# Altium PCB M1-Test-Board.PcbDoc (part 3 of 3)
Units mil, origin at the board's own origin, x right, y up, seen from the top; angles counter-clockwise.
Board outline 3977 x 5000 mil, 4 copper layers (Top, GND Layer 2, Power Layer 3, Bottom), stack 60 mil thick; 191 components, 124 nets, 579 pads, 189 vias.
Unrouted connection lines stored in the file: 80.
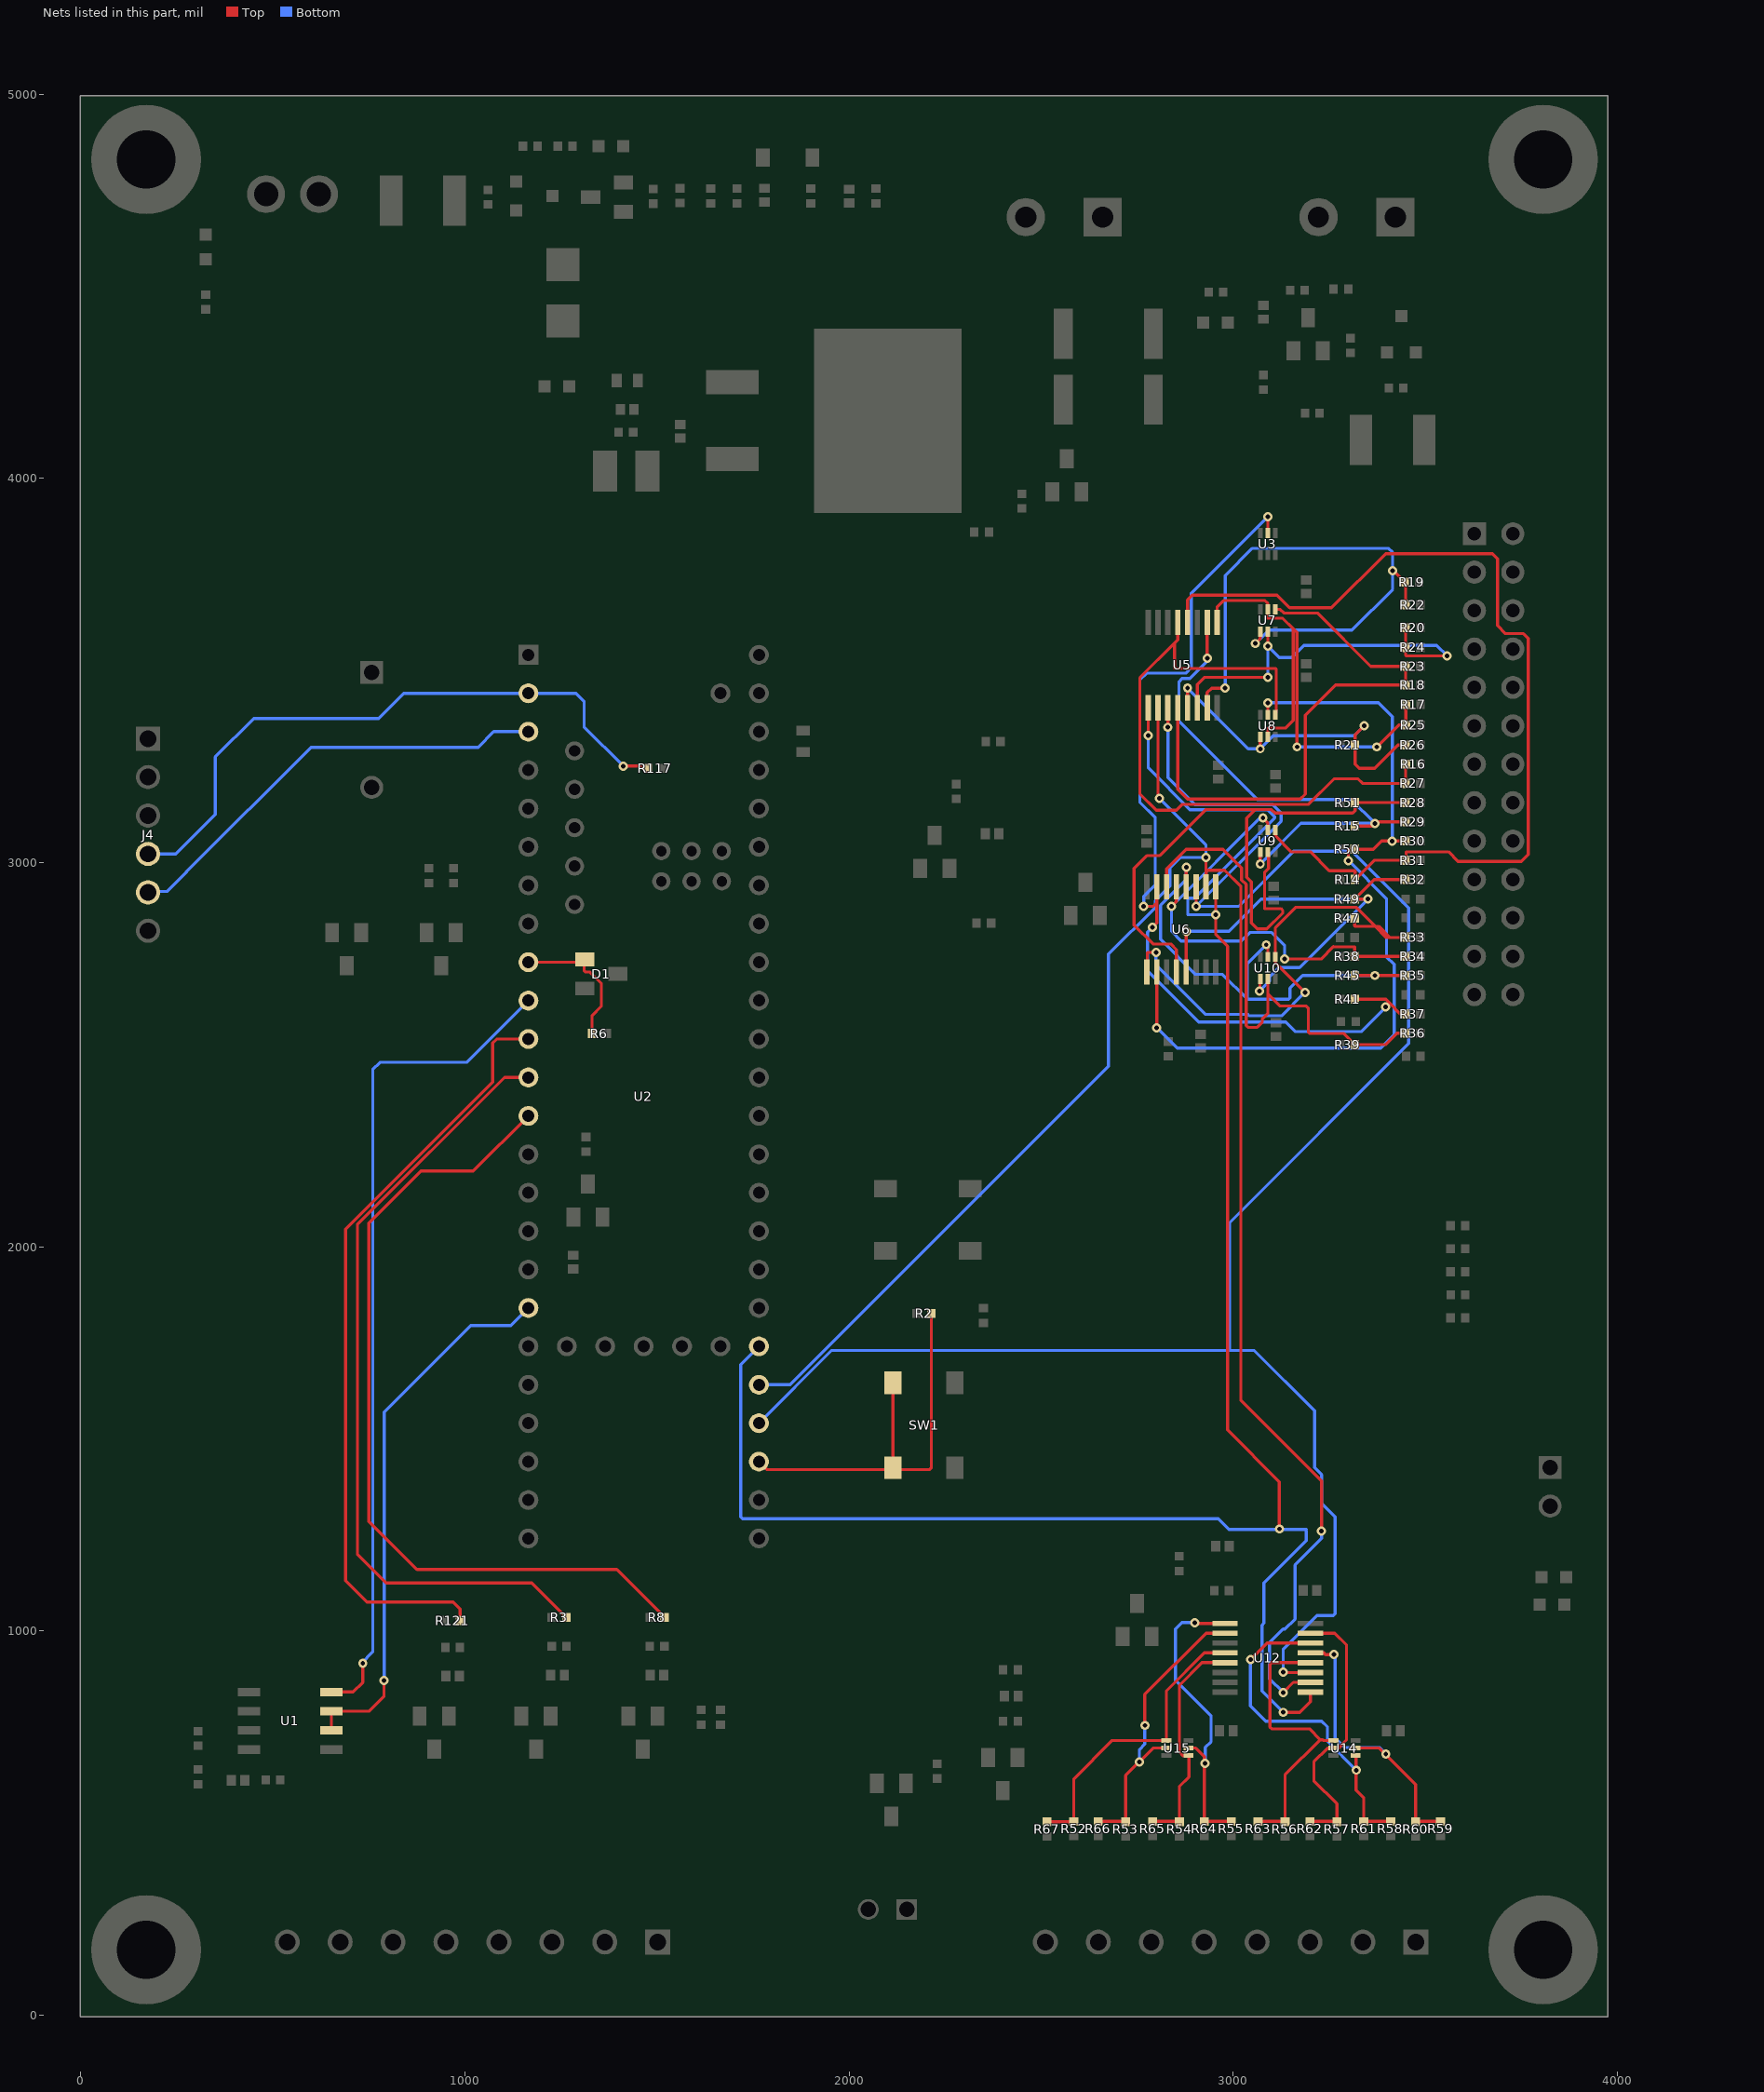
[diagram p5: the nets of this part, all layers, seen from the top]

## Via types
v1: diameter 24, hole 12, Top to Bottom, 186 vias
v2: diameter 50, hole 28, Top to Bottom, 3 vias

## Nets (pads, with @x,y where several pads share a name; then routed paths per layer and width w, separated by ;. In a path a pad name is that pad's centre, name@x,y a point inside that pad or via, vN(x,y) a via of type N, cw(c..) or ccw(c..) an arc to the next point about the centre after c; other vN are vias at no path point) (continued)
NetU2_36: U2.36 U5.11 U6.11 U12.11 | length 5366.6
  Top w8: v1(2830,3352) U5.11@2830,3403 ; v1(2903.39,2886) U6.11@2903.39,2937 ; v1(3130.38,892.95) 3131.72,891.61 U12.11@3201,891.61
  Bottom w8: U2.36@1765.2,1540.63 1954.57,1730 2985.31,1730 ; v1(2830,3352) 2830,3220.93 2900,3150.93 3102.76,3150.93 3125,3128.69 3125,3107.61 v1(2903.39,2886) 3014,2886 3157.64,3029.64 3309.36,3029.64 3457,2882 3457,2529 2990,2062 2990,1734.69 2985.31,1730 ; v1(3130.38,892.95) 3130.38,952.66 3217.72,1040 3260.31,1040 3265,1044.69 3265,1297.16 3230,1332.16 3230,1406.7 3211.7,1425 3211.7,1573.3 3055,1730 2985.31,1730
NetU2_37: U2.37 U5.10 U6.10 U12.10 | length 4949.5
  Top w8: U5.10@2804.41,3403 2804.41,3170.59 v1(2808,3167) ; v1(2928.98,3013) U6.10@2928.98,2937 2929.98,2980 2977.5,2980 3020,2937.5 3020,1600 3230,1390 v1(3230,1260) ; v1(3130.38,839.64) 3156.76,866.02 U12.10@3201,866.02
  Bottom w8: U2.37@1765.2,1640.63 1846.11,1640.63 2675,2469.52 2675,2761.5 2797,2883.5 2797,2900.74 2835,2938.74 2835,2986.07 2861.93,3013 v1(2928.98,3013) 2928.98,3046.02 v1(2808,3167) ; v1(3130.38,839.64) 3094.68,875.33 3094.68,969.68 3130,1005 3135,1005 3160.79,1030.79 3160.79,1171.49 3230,1240.7 v1(3230,1260)
NetU2_38: U2.38 U5.9 U6.9 U12.9 | length 5308.4
  Top w8: v1(2778.82,3331) U5.9@2778.82,3403 ; U6.9@2954.57,2937 v1(2954.57,2864) 2954.57,2812.5 2985.07,2782 2985.07,1522.93 3120,1388 v1@3120,1265 ; v1(3130.38,787.95) 3172.95,787.95 3201,816 U12.9@3201,840.43
  Bottom w8: U2.38@1765.2,1740.63 1717.86,1693.3 1717.86,1296.34 1722.55,1291.66 2961.34,1291.66 2989.08,1263.92 3120.87,1263.92 3190,1263.92 ; v1(2778.82,3331) 2778.82,3246.11 2887.5,3137.43 3089.57,3137.43 3108,3119 3108,3116 2899.5,2907.5 2883,2907.5 2881.89,2906.39 2881.89,2865 2882.89,2864 v1(2954.57,2864) ; v1(3130.38,787.95) 3075,843.33 3075,1015 3080,1020 3080,1080 3080,1125 3190,1235 3190,1260
  other v1: 3120.87,1265.28
P6V-1: R20.2 R24.2 U5.14 U7.5 | length 1054.8
  Top w8: U5.14@2906.77,3403 2906.77,3463.77 2925,3482 v1(3090,3482) ; v1(3090,3563.5) U7.5@3090,3601.06 ; R20.2@3448.91,3611 R24.2@3448.91,3559.79 3448.91,3539 3449.91,3538 v1(3557,3538)
  Bottom w8: v1(3090,3482) v1(3090,3563.5) 3120,3533.5 3152.5,3533.5 3184,3565 3530,3565 v1(3557,3538)
P6V-2: R19.2 R22.1 U5.15 U7.4 | length 1501.3
  Top w8: U5.15@2932.36,3403 2932.36,3442.36 2944,3454 v1(2979,3454) ; v1(3057.81,3570.07) 3070.31,3582.57 U7.4@3070.31,3601.06 ; v1(3415,3760) 3416.69,3760 3445.91,3730.79 R19.2@3445.91,3730 ; R22.1@3448.91,3671 R19.2@3448.91,3727
  Bottom w8: v1(2979,3454) 2979,3747 3050,3818 3404,3818 3415,3807 3415,3711 3309.07,3605.07 3092.81,3605.07 v1(3057.81,3570.07)
P6V-3: R18.2 R23.1 U5.12 U7.1 | length 1509.3
  Top w8: U5.12@2855.59,3403 2855.59,3190.41 2881,3165 3175,3165 3188,3178 3188,3383.5 3266.52,3462.02 R18.2@3448.91,3462.02 R23.1@3448.91,3511 3358,3511 3219.5,3649.5 3131.44,3649.5 3122,3658.94 U7.1@3109.69,3658.94
P12V-1: R17.2 R25.1 U5.1 U7.2 U8.5 | length 1305.6
  Top w8: U5.1@2957.95,3625 2957.95,3664.95 2975,3682 3082.93,3682 3090,3674.93 U7.2@3090,3658.94 3090,3637 3091,3636 3129,3636 3156.18,3608.82 ; U8.5@3090,3327.06 3090,3349 3091,3350 3136,3350 3156.18,3370.18 3156.18,3608.82 ; v1(3166,3301) 3166,3599 3156.18,3608.82 ; v1(3374,3301) 3430.95,3357.95 R25.1@3449.81,3357.95 R17.2@3449.81,3411
  Bottom w8: v1(3166,3301) v1(3374,3301)
P12V-2: R21.2 R26.2 U5.13 U8.4 | length 903.3
  Top w8: U5.13@2881.18,3403 v1(2881.18,3454) ; v1(3070.31,3296.07) U8.4@3070.31,3327.06 ; v1(3341,3356) 3317.09,3332.09 R21.2@3317.09,3306 3317.09,3256.5 3328.59,3245 3368,3245 3429,3306 R26.2@3448.91,3306
  Bottom w8: v1(2881.18,3454) 3039.11,3296.07 v1(3070.31,3296.07) 3104.43,3330.19 3315.19,3330.19 v1(3341,3356)
R_G1: R34.1 R38.1 U6.13 U9.2 | length 1205.9
  Top w8: v1(2839.5,2886) 2852.2,2898.7 U6.13@2852.2,2937 ; v1(3077.5,3115.93) 3090,3103.43 U9.2@3090,3084.94 ; v1(3134,2749) 3229,2749 3261,2781 3316.19,2780 R38.1@3316.19,2756 R34.1@3448.91,2756
  Bottom w8: v1(3077.5,3115.93) 3069.43,3115.93 v1(2839.5,2886) 2839.5,2821 2864.5,2796 3021,2796 3043,2818 3100,2818 3134,2784 v1(3134,2749)
R_G2: R36.1 R39.1 U6.14 U10.5 | length 1329
  Top w8: U6.14@2826.61,2937 2826.61,2984 2877.11,3034.5 2973.5,3034.5 3021.81,2986.19 3021.81,2954.78 3033.5,2943.09 3033.5,2575.73 3038.19,2571.05 3062.5,2571.05 3075.55,2584.1 3075.55,2592.55 3090,2607 3090,2658.5 ; U10.5@3090,2696.85 3090,2658.5 ; R36.1@3448.91,2556 3426,2556 3396,2526 R39.1@3317.09,2526 3288.09,2555 3200.09,2555 3195.41,2559.69 3195.41,2621.59 3190.53,2626.47 3122.03,2626.47 3090,2658.5
R_G3: R32.2 R49.2 U6.5 U10.4 | length 1222.2
  Top w8: U6.5@2877.79,2715 v1(2877.79,2821) ; v1(3068.5,2665.86) 3069.41,2666.77 3069.41,2695.95 U10.4@3070.31,2696.85 ; v1(3351,2904.98) R49.2@3316.19,2904.98 3367.21,2956 R32.2@3448.91,2956
  Bottom w8: v1(2877.79,2821) 2989,2821 3072.98,2904.98 v1(3351,2904.98) 3172.75,2726.73 3118.69,2726.73 3095.12,2703.17 3095.12,2692.48 v1(3068.5,2665.86)
R_G4: R33.2 R47.2 U6.1 U10.1 | length 1294.3
  Top w8: U6.1@2775.43,2715 2776.43,2766 v1(2799,2766) ; v1(3187,2662) 3109.68,2739.32 U10.1@3109.69,2754.73 3109.68,2830.3 3163.05,2883.67 3301.23,2883.67 3319.9,2883.67 3369.57,2834 ; R47.2@3316.19,2855 3316.19,2835 3317.19,2834 3369.57,2834 ; R33.2@3448.91,2806 3448.91,2804.69 3408,2804.69 ; 3369.57,2834 3398.88,2804.69 3408,2804.69 ; 3369.57,2834 3378.69,2834 3408,2804.69
  Bottom w8: v1(2799,2766) 2799,2733.5 2927.5,2605 3037.59,2605 3041.59,2601 3126,2601 v1(3187,2662)
R_G5: R35.2 R45.2 U6.12 U10.2 | length 1256.1
  Top w8: U6.12@2877.79,2937 v1(2877.79,2988) ; v1(3086,2786) 3090,2782 U10.2@3090,2754.73 ; R45.2@3317.09,2706 v1(3369,2706) R35.2@3448.91,2706
  Bottom w8: v1(2877.79,2988) 2877.79,2955.29 2811,2888.5 2811,2800 2902,2709 2972,2709 3036,2645 ; v1(3086,2786) 3036,2736 3036,2645 ; v1(3369,2706) 3180.99,2706 3147.84,2672.85 3147.84,2647.84 3144,2644 3037,2644 3036,2645
R_G6: R37.2 R41.2 U3.2 U6.15 | length 2422.9
  Top w8: v1(2767,2886) 2792.02,2886 2801.02,2895 ; v1(2789.5,2831) 2801.02,2842.52 2801.02,2895 ; U6.15@2801.02,2937 2801.02,2895 ; U3.2@3090,3857.87 v1(3090,3900) ; R41.2@3317.09,2644.19 3397.22,2644.19 3407.2,2634.2 ; v1(3397,2624) 3407.2,2634.2 ; R37.2@3448.91,2606 3435.41,2606 3407.2,2634.2
  Bottom w8: v1(2767,2886) 2767,2912 2797,2942 2797,3117 2757,3157 2757,3475 2775,3493 2876,3493 2891,3508 2891,3701 v1(3090,3900) ; v1(2789.5,2831) 2777,2818.5 2777,2718 2910,2585 3137,2585 3162,2560 3333,2560 v1(3397,2624)
R_nRst: R15.2 R29.1 U5.2 U9.4 | length 1429.5
  Top w8: v1(2932.36,3532) U5.2@2932.36,3625 ; v1(3070.31,2996.07) U9.4@3070.31,3027.06 ; R15.2@3317.09,3095 3362,3095 v1(3369,3102) 3373,3106 R29.1@3448.91,3106
  Bottom w8: v1(2932.36,3532) 2932.36,3523.86 2887.5,3479 2867,3479 2859,3471 2859,3368 3062.57,3164.43 3306.57,3164.43 v1(3369,3102) 3176.24,3102 v1(3070.31,2996.07)
R_S0: R30.2 R50.2 U6.2 U8.2 | length 2182.6
  Top w8: v1(2801,2570) U6.2@2801.02,2715 ; U8.2@3090,3384.94 v1(3090,3416) ; v1(3300,3005) 3300,3033.79 3301,3034.79 R50.2@3316.19,3034.79 3364.79,3034.79 3386,3056 v1(3414,3056) R30.2@3448.91,3056
  Bottom w8: v1(2801,2570) 2854,2517 3384,2517 3419,2552 3419,2735 3399,2755 3399,2906 v1(3300,3005) ; v1(3090,3416) 3378,3416 3414,3380 v1(3414,3056)
R_S1: R16.2 R27.1 U5.5 U8.1 | length 1736.7
  Top w8: U5.5@2855.59,3625 2855.59,3579.59 2847,3571 ; U8.1@3109.69,3384.94 3109.68,3388 3112,3390.32 3112,3504 3111,3505 2848,3505 2847,3506 2847,3571 ; R16.2@3449.81,3256 3448.91,3255.09 R27.1@3448.91,3206 3337,3206 3325,3218 3263,3218 3196.5,3151.5 2867.5,3151.5 2852,3136 2800,3136 2757,3179 2757,3481 2847,3571
R_S2: R28.2 R51.2 U6.4 U9.5 | length 1764.5
  Top w8: U6.4@2852.2,2715 2852.2,2773.3 2837.5,2788 2791.04,2788 2742.02,2837.02 2742.02,2985.02 2775,3018 2808,3018 2928,3138 3057.36,3138 ; U9.5@3090,3027.06 3090,3020 3092,3020 3092,2984.5 3081.5,2974 3081.5,2881 3082.5,2880 3124.29,2880 3128.98,2875.31 3128.98,2868.69 3087.29,2827 3062.5,2827 3047,2842.5 3047,2950.03 3035.31,2961.71 3035.31,3115.95 3057.36,3138 ; R28.2@3448.91,3156 R51.2@3317.09,3156 3317.09,3135 3310.95,3128.85 3108.85,3128.85 3099.71,3138 3057.36,3138
R_S7: R14.2 R31.1 U5.4 U9.1 | length 2571.9
  Top w8: U5.4@2881.18,3625 2881.18,3683.5 2893.68,3696 3114,3696 3147,3663 3256,3663 3397,3804 3675,3804 3688,3791 3688,3617 3709,3596 3755.5,3596 3768,3583.5 3768,3021 3750,3003 3585.5,3003 3560.5,3028 3449.91,3028 R31.1@3448.91,3005.88 3366.98,3005.88 R14.2@3317.09,2956 3317.09,2978 3316.09,2979 3250,2979 3201,3028 3150.68,3028 3109.68,3069 U9.1@3109.69,3084.94
RX1: J4.4 R117.1 U2.0 | length 1682.3
  Top w8: v1(1412,3251) 1456.88,3251 1462.88,3245 R117.1@1475.91,3245
  Bottom w8: J4.4@175,3022.42 247.42,3022.42 350,3125 350,3275 450,3375 775,3375 840.63,3440.63 U2.0@1165.2,3440.63 1289.37,3440.63 1310,3420 1310,3353 v1(1412,3251)
RX2: D1.1 R6.1 U2.7 | length 362.2
  Top w8: U2.7@1165.2,2740.63 1304.63,2740.63 1310,2735.26 1310,2719.69 1314.69,2715 1325,2715 1330,2710 1330.44,2710 1355,2685.44 1355,2625.87 1330.91,2601.78 R6.1@1330.91,2555
Sol1: R121.1 U2.9 | length 2013.9
  Top w8: R121.1@987.09,1027 987.09,1057 969.09,1075 745,1075 689.09,1130.91 689.09,2045.87 1072,2428.77 1072,2530 1082.63,2540.63 U2.9@1165.2,2540.63
Sol2: R3.1 U2.10 | length 2073.9
  Top w8: U2.10@1165.2,2440.63 1102.95,2440.63 720,2057.68 720,1200 795,1125 1174.09,1125 R3.1@1264.09,1035
Sol3: R8.1 U2.11 | length 2181.1
  Top w8: U2.11@1165.2,2340.63 1021.57,2197 885.31,2197 750,2061.69 750,1285 875,1160 1395.09,1160 R8.1@1520.09,1035
TargetPower: R2.1 SW1.3 SW1.4 U2.35 | length 1085.9
  Top w8: U2.35@1765.2,1440.63 1785.83,1420 2109.79,1420 SW1.3@2114.29,1424.5 ; SW1.4@2114.29,1645.5 SW1.3@2114.29,1424.5 ; R2.1@2214.09,1826.16 2214.09,1724.94 2214.29,1724.74 2214.29,1424.69 2209.61,1420 2118.79,1420 SW1.3@2114.29,1424.5
TX1: J4.5 U2.1 | length 1164
  Bottom w8: J4.5@175,2922.42 177.58,2925 225,2925 275,2975 275,2976 599,3300 1034.37,3300 1075,3340.63 U2.1@1165.2,3340.63
TX2: U1.4 U2.8 | length 2180.4
  Top w8: U1.4@652.25,841 709,841 734,866 v1(734,916)
  Bottom w8: v1@730,915 760,945 760,2461.52 778.48,2480 1004.57,2480 U2.8@1165.2,2640.63
Uart2Dir: U1.2 U1.3 U2.26 | length 1431.9
  Top w8: U1.2@652.25,741 U1.3@652.25,791 751,791 789,829 v1(789,871)
  Bottom w8: v1@789.83,870 789.83,1569.83 1015,1795 1119.57,1795 U2.26@1165.2,1840.63
V12_1: R59.2 R60.1 U12.13 U14.5 | length 789.1
  Top w8: U12.13@3201,942.8 3236,942.8 3240.3,938.5 v1(3262.48,938.5) ; U14.5@3318.94,695 3380,695 3475,600 R60.1@3475,503.19 3475.9,504.09 R59.2@3540,504.09
  Bottom w8: v1@3265,940 3265,721.54 3290,696.54 3380.44,696.54 v1(3397.42,679.56)
V12_2: R58.2 R61.1 U12.14 U14.4 | length 910.5
  Top w8: v1(3045,925) 3088.39,968.39 U12.14@3201,968.39 ; U14.4@3318.94,675.32 3320,674.25 3320,585 3340,565 R61.1@3340,504.09 R58.2@3410,504.09
  Bottom w8: v1(3045,925) 3045,805 3085,765 3230.31,765 3245.31,750 3245.31,712.5 v1(3320.25,637.56)
V33_1: R57.2 R62.1 U12.15 U14.2 | length 714.9
  Top w8: R62.1@3200,504.09 3269.1,504.09 R57.2@3270,503.19 3270,550 3210,610 3210,658.93 3246.07,695 U14.2@3261.06,695 3276.06,695 3276.06,697.15 3295,716.09 3295,963.39 3264.42,993.98 U12.15@3201,993.98
V33_2: R56.2 R63.1 U12.12 U14.1 | length 772.3
  Top w8: R63.1@3065,504.09 3134.1,504.09 R56.2@3135,503.19 3135,625 3226.69,716.69 ; U12.12@3201,917.21 3100.12,917.21 3095.44,912.52 3095.44,749.69 3100.12,745 3198.37,745 3226.69,716.69 ; U14.1@3261.06,714.68 3235.32,714.69 3233.31,716.69 3226.69,716.69
V33_3: R55.2 R64.1 U12.1 U15.5 | length 822.8
  Top w8: U15.5@2883.94,695 2902.42,695 2925,672.42 R64.1@2925,504.09 R55.2@2995,504.09 ; v1@2896.93,1019.57 U12.1@2979,1019.57
  Bottom w8: v1(2900.38,1021.57) 2866.57,1021.57 2850,1005 2850,870.94 2942.44,778.5 2942.44,712.05 2926.93,696.54 v1(2926.93,655)
V33_4: R54.2 R65.1 U12.5 U15.4 | length 598.6
  Top w8: R65.1@2790,504.09 2859.1,504.09 R54.2@2860,503.19 2860,595 2885,620 2885,674.25 U15.4@2883.94,675.32 2868.94,675.32 2860,684.26 2860,858.61 2918.59,917.21 U12.5@2979,917.21
V33_5: R53.2 R66.1 U12.2 U15.2 | length 784.6
  Top w8: R66.1@2648.82,504.09 2719.1,504.09 R53.2@2720,503.19 2720,623.9 2791.1,695 U15.2@2826.06,695 ; v1(2770,754) 2770,834.62 2929.36,993.98 U12.2@2979,993.98
  Bottom w8: v1(2755.87,658.69) 2755.87,690.87 2770,705 v1(2770,754)
V33_6: R52.2 R67.1 U12.4 U15.1 | length 786.7
  Top w8: R67.1@2515,503.19 2584.1,503.19 R52.2@2585,504.09 2585,615 2684.69,714.69 U15.1@2826.06,714.68 2826.06,843.77 2925.09,942.8 U12.4@2979,942.8
pads on no net: D1.2 D4.1 J4.2 J4.3 J4.6 J5.1 J5.2 J5.4 J5.21 U2.2 U2.3 U2.3.3V_1 U2.3.3V_3 U2.5 U2.5V U2.6 U2.12 U2.13 U2.24 U2.27 U2.28 U2.29 U2.30 U2.31 U2.32 U2.D+ U2.D- U2.GND5 U2.LED U2.ON/OFF U2.PROGRAM U2.R+ U2.R- U2.T+ U2.T- U2.USB_GND1 U2.USB_GND2 U2.VBAT U2.VUSB U3.1

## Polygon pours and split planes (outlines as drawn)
GND on Bottom "GND_L04_P001" (solid, remove dead copper, pour order 1): -10,5005 3980,5005 3980,-20 20,-20 -5,5
GND on Top "GND_L01_P000" (solid, remove dead copper, pour order 0): -4.25,4992.22 0.82,4997.29 3967.75,4997.29 3967.75,-0.15 3969.32,-1.72 0.3,-1.72 -2.25,0.83 -2.25,482.29
+3.3V on Power Layer 3 (split plane): 186 vertices, not listed, extent 8.09,6.09 3964.91,4985.91
+5V on Power Layer 3 (split plane): 366.93,4575 367.21,4572.91 368.01,4570.97 369.29,4569.29 374.29,4564.29 375.97,4563.01 377.91,4562.21 380,4561.93 616.93,4561.93 616.93,4360 616.93,4165.2 616.93,3970 617.21,3967.91 618.01,3965.97 619.29,3964.29 914.29,3669.29 915.97,3668.01 917.91,3667.21 920,3666.93 1365,3666.93 1367.09,3667.21 1369.03,3668.01 1370.71,3669.29 1430.71,3729.29 1431.99,3730.97 1432.79,3732.91 1433.07,3735 1433.07,4171.62 1796.97,4171.62 1876.93,4091.66 1876.93,4060 1876.93,4050 1876.93,3408.07 1525,3408.07 1523.15,3407.83 1522.91,3407.79 1520.97,3406.99 1519.29,3405.71 1509.29,3395.71 1508.01,3394.03 1507.21,3392.09 1506.93,3390 1506.93,3176.34 1507.21,3174.25 1508.01,3172.3 1509.29,3170.63 1509.96,3169.96 1511.63,3168.68 1513.58,3167.87 1515.67,3167.6 1517.76,3167.87 1517.89,3167.93 1871.93,3167.93 1871.93,2765 1872.21,2762.91 1873.01,2760.97 1874.29,2759.29 1929.29,2704.29 1930.97,2703.01 1932.91,2702.21 1933.15,2702.17 1935,2701.93 2640,2701.93 2642.09,2702.21 2644.03,2703.01 2645.71,2704.29 2736.96,2795.54 2738.24,2797.22 2739.04,2799.16 2739.32,2801.25 2739.04,2803.34 2738.24,2805.28 2738.07,2805.5 2738.07,2830 2738.07,2925 2738.07,3966.93 3576.93,3966.93 3576.93,2115 3576.93,2114.99 3576.93,2114.97 3582.06,623.07 2858.07,623.07 2858.07,1275 2857.79,1277.09 2856.99,1279.03 2855.71,1280.71 2854.03,1281.99 2852.09,1282.79 2850,1283.07 2193.07,1283.07 2193.07,1931.66 2373.34,2111.93 2495,2111.93 2497.09,2112.21 2497.5,2112.38 2497.91,2112.21 2500,2111.93 2675,2111.93 2677.09,2112.21 2679.03,2113.01 2680.71,2114.29 2695.71,2129.29 2696.99,2130.97 2697.79,2132.91 2698.07,2135 2697.79,2137.09 2697.62,2137.5 2697.79,2137.91 2698.07,2140 2698.07,2305 2697.79,2307.09 2696.99,2309.03 2696.25,2310 2696.99,2310.97 2697.79,2312.91 2698.07,2315 2697.79,2317.09 2696.99,2319.03 2695.71,2320.71 2685.71,2330.71 2684.03,2331.99 2682.09,2332.79 2680,2333.07 1010,2333.07 1007.91,2332.79 1005.97,2331.99 1004.29,2330.71 1003.01,2329.03 1002.21,2327.09 1001.93,2325 1001.93,578.34 946.66,523.07 10,523.07 8.09,522.82 8.09,4985.91 366.93,4985.91
+12V on Power Layer 3 (split plane): 3144.29,4984.29 3381.93,4746.66 3381.93,4308.07 2666,4308.07 2665.5,4308 2665,4308.07 2393.07,4308.07 2393.07,4745 2392.79,4747.09 2391.99,4749.03 2390.71,4750.71 2389.03,4751.99 2387.09,4752.79 2385,4753.07 2120,4753.07 2117.91,4752.79 2115.97,4751.99 2114.29,4750.71 2070.05,4706.46 2068.77,4704.79 2067.96,4702.84 2067.69,4700.75 2067.69,4453.07 1298.34,4453.07 1175.71,4575.71 1174.03,4576.99 1172.09,4577.79 1170,4578.07 383.34,4578.07 383.07,4578.34 383.07,4985.91 3143.05,4985.91
GND on GND Layer 2 (split plane): 3964.91,6.09 8.09,6.09 8.09,4985.91 3964.91,4985.91

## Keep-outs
Keep-Out Layer:
  lines w34: 3973.34,-4 -1.07,-4 -1.07,4996.07 2.86,5000 3975,5000 3975.5,-3.29

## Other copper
Power Layer 3 (plane layer: these items are gaps in the copper):
  lines w16: 10,515 950,515 1010,575 1010,2325 2680,2325 2690,2315 ; 375,4995 375,4575 380,4570 1170,4570 1295,4445 2075.75,4445 2075.75,4700.75 2120,4745 2385,4745 2385,4300 2665,4300 ; 625,4570 625,4360 625,4165.2 625,3970 920,3675 1365,3675 1425,3735 1425,4179.69 1800.31,4179.69 1885,4095 1885,4050 ; 1515.67,3175.67 1515,3176.34 1515,3390 1525,3400 1880,3400 ; 1517.88,3176 1880,3176 1880,2765 1935,2710 2090,2710 2345,2710 2640,2710 2731.25,2801.25 2730,2802.5 2730,2830 2730,2925 2730,3975 3585,3975 3585,2115 3590.16,615 2850,615 ; 1885,3400 1885,4060 ; 2185,1280 2185,1275 ; 2495,2120 2370,2120 2185,1935 2185,1275 ; 2500,2120 2675,2120 2690,2135 ; 2666,4300 3390,4300 3390,4750 3150,4990 ; 2690,2140 2690,2305 ; 2850,620 2850,1275 2185,1275

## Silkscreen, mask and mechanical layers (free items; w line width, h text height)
Silkscreen Top:
  lines w4: 2470,1290 2485,1275 3472.21,1275 3495,1297.79 3495,1542.3 3457.3,1580 2510,1580 2470,1540 2470,1505 2470,1290
  lines w8: 538,250 538,460 ; 675,250 675,460 ; 811.34,257.48 811.34,459.92 ; 945,257.48 945,465 ; 1088.83,257.48 1088.83,461.08 ; 1223.39,465.44 1225,257.48 ; 1363.83,260 1363.83,461.08 ; 1505,260 1505,460 ; 2513.83,1310 2513.83,1381.08 ; 2643.83,1310 2643.83,1381.08 ; 2787.18,1310 2787.18,1381.08 ; 2923.83,1310 2923.83,1381.08 ; 3063.83,1306.21 3063.83,1377.29 ; 3203.83,1305 3203.83,1376.08 ; 3338.83,1306.21 3338.83,1377.29 ; 3463.83,1305 3463.83,1376.08
  text "Batt Sim On" at 1280,4935.44 h60
  text "-" at 615,4636.09 h80
  text "+" at 470,4631.52 h80
  text "Power" at 1978,4560.89 h120
  text "Batt" at 3690,4555.89 h120
  text "-" at 2450,4529.11 h120
  text "-" at 3212,4529.11 h120
  text "+" at 2640,4524.78 h120
  text "+" at 3405,4524.78 h120
  text "Power-In" at 375,4520.89 h120
  text "12V/2A" at 405,4428.44 h120
  text "Cntr On" at 2869.27,4300.44 h60
  text "+5 Volt" at 1025,4220.76 h60
  text "Debug" at 337.45,2957.79 h120 r90
  text "Boot Target" at 1980,2376.39 h120
  text "LenelS2, Carrier Corp" at 125,2347.44 h120
  text "M1-3200 Test Fixture" at 125,2215.89 h120
  text "1" at 3892,2144 h60 r90
  text "Rev  C" at 125,2075.89 h120
  text "Panel LED" at 3854.11,1530 h120 r90
  text "1" at 3840,1490 h60 r90
  text "P3.2" at 2529.65,1400 h60 r90
  text "TP33" at 2664.65,1400 h60 r90
  text "TP35" at 2804.65,1400 h60 r90
  text "TP34" at 2939.65,1400 h60 r90
  text "TP31" at 3079.65,1400 h60 r90
  text "TP36" at 3209.65,1400 h60 r90
  text "TP25" at 3354.65,1400 h60 r90
  text "BatCell" at 3474.56,1400 h60 r90
  text "Target Power" at 1920,1312.55 h120
  text "RS-485" at 540,535.44 h60
  text "GND" at 1052.5,476.6 h60
  text "GND" at 1327.5,476.6 h60
  text "A" at 525,475.17 h60
  text "B" at 665,475 h60
  text "GND" at 775,475.44 h60
  text "Sol 1" at 959.56,475 h60 r90
  text "Sol 2" at 1236.49,475 h60 r90
  text "Sol 3" at 1519.65,475 h60 r90
  text "8" at 2390,305.44 h60
  text "Tamper" at 1665,147.44 h120
  text "1" at 3584,88 h60
  text "1" at 1645,65 h60
  text "8" at 375,60.44 h60
  text "2" at 1530,38 h60
Board Outline:
  lines w10: 0.3,-1.88 3975.5,-1.88 -3.12,-1.88 3.45,4.69 3.45,4988.04 15.41,5000 3975,5000 ; 3975.5,-3.29 3975.5,5000
Drill Drawing:
  drawing of 394 lines, arcs and shapes, not listed
  text "Notes:" at 9959,5722.86 h120
  text "Layer" at 4636.16,5583.58 h117.16
  text "Name" at 5126.52,5583.58 h117.16
  text "Material" at 6377.62,5583.58 h117.16
  text "Thickness" at 7229.81,5583.58 h117.16
  text "Constant" at 7929.81,5583.58 h117.16
  text "Board Layer Stack" at 8577.67,5583.58 h117.16
  text "1.  LATEST VERSION OF ALL REFERENCED SPECIFICATIONS TO BE USED UNLESS" at 10062.5,5492.86 h120
  text "Silkscreen Top" at 5126.52,5349.26 h117.16
  text "OTHERWISE SPECIFIED." at 10262.5,5292.86 h120
  text "Solder Mask Top" at 5126.52,5114.95 h117.16
  text "Solder Resist" at 6377.62,5114.95 h117.16
  text "1.00mil" at 7229.81,5114.95 h117.16
  text "3.2" at 7929.81,5114.95 h117.16
  text "2.  FABRICATE IN ACCORDANCE WITH IPC-6012B, CLASS 2  UNLESS" at 10062.5,5092.86 h120
  text "OTHERWISE SPECIFIED." at 10262.5,4892.86 h120
  text "Top Surface Plating" at 5126.52,4880.64 h117.16
  text "Lead-Free" at 6377.62,4880.64 h117.16
  text "1.40mil" at 7229.81,4880.64 h117.16
  text "3.  INSPECT IN ACCORDANCE WITH IPC-6012B, CLASS 2 UNLESS OTHERWISE" at 10061,4683.86 h120
  text "1" at 4636.16,4646.33 h117.16
  text "Top" at 5126.52,4646.33 h117.16
  text "0.70mil" at 7229.81,4646.33 h117.16
  text "SPECIFIED." at 10331,4533.86 h120
  text "Dielectric 1" at 5126.52,4412.02 h117.16
  text "2 x 2116" at 6377.51,4412.02 h117.16
  text "9.10mil" at 7229.81,4412.02 h117.16
  text "4.3" at 7929.81,4412.02 h117.16
  text "4.  MATERIAL:" at 10061,4288.86 h120
  text "2" at 4636.05,4177.71 h117.16
  text "GND Layer 2" at 5126.52,4177.71 h117.16
  text "0.70mil" at 7229.81,4177.71 h117.16
  text "HIGH TEMP FR4 (OR EQUIVALENT FOR ROHS COMPLIANCE)." at 10353.75,4085.61 h120
  text "Dielectric2" at 5126.52,3943.4 h117.16
  text "Core" at 6377.62,3943.4 h117.16
  text "39.00mil" at 7229.81,3943.4 h117.16
  text "4.6" at 7929.81,3943.4 h117.16
  text "FLAME RETARDENT, IN ACCORDANCE WITH UL STANDARD 796." at 10353.75,3920.61 h120
  text "FINISHED BOARD MUST MEET UL94V-0." at 10353.75,3745.61 h120
  text "3" at 4636.16,3709.08 h117.16
  text "Power Layer 3" at 5126.52,3709.08 h117.16
  text "0.70mil" at 7229.81,3709.08 h117.16
  text "5.  SILKSCREEN NOMENCLATURE NOT TO COVER ANY PORTION OF A COMPONENT" at 10065.15,3542.11 h120
  text "Dielectric3" at 5126.52,3474.77 h117.16
  text "2 x 2116" at 6377.51,3474.77 h117.16
  text "9.10mil" at 7229.81,3474.77 h117.16
  text "4.3" at 7929.81,3474.77 h117.16
  text "PAD. FABRICATOR TO CLIP ANY NON-CONFORMING SILKSCREEN NOMENCLATURE." at 10265.15,3342.11 h120
  text "4" at 4636.16,3240.46 h117.16
  text "Bottom" at 5126.52,3240.46 h117.16
  text "0.70mil" at 7229.81,3240.46 h117.16
  text "DO NOT REMOVE SILKSCREEN FROM TENTED VIAS. SILKSCREEN COLOR: WHITE." at 10265.15,3142.11 h120
  text "Bottom Surface Finish" at 5126.52,3006.15 h117.16
  text "Lead-Free" at 6377.62,3006.15 h117.16
  text "1.40mil" at 7229.81,3006.15 h117.16
  text "6.  USE LPI SOLDER MASK OVER BARE COPPER PER IPC-SM-840C, CLASS 2." at 10051.15,2891.11 h120
  text "Solder Mask Bottom" at 5126.52,2771.84 h117.16
  text "Solder Resist" at 6377.62,2771.84 h117.16
  text "1.00mil" at 7229.81,2771.84 h117.16
  text "3.2" at 7929.81,2771.84 h117.16
  text "SOLDERMASK COLOR: BLUE." at 10336,2691.86 h120
  text "Silkscreen Bottom" at 5126.52,2537.53 h117.16
  text "7.  GLOBAL AND LOCAL FIDUCIALS MUST BE FREE OF ANY MARKINGS." at 10061,2441.86 h120
  text "8. REMOVAL OF NON-FUNCTIONAL PADS ON INNER LAYERS ALLOWED." at 10061,2146.86 h120
  text "9. THEIVING OF OUTER LAYERS IS ACCEPTABLE AS LONG AS THE COPPER IS" at 10061,1846.86 h120
  text "KEPT A MININMUM OF 0.200\" FROM ANY DESIGN FEATURE." at 10361,1646.86 h120
  text "10. PRIOR TO BOARD FABRICATION, COMPARE GERBER DATA TO SUPPLIED" at 10061,1446.86 h120
  text "IPC-D-356A NETLIST. REPORT ALL DISCREPANCIES." at 10361,1246.86 h120
  text "11. ENTIRE BOARD TO BE IMMERSION GOLD PLATED. 2 TO 5 MICROINCHES" at 10061,946.86 h120
  text "OVER 100 MICROINCHES MINIMUM OF ELECTROLESS NICKEL." at 10186,746.86 h120
  text "12. BOARD TO BE ROHS COMPATIBLE." at 10074.08,461.31 h120
  text "13. ANY CHANGES TO THE SUPPLIED GERBER DATA TO BE APPROVED BY S2 SECURITY." at 10070,235 h120
  text "Rev A - Initial" at 7440,-930 h120
  text "Rev B - Added BJT Q11 & Q12 to control boot target" at 7440,-1055 h120
  text "Symbol" at -64.04,-1618.13 h95.99
  text "Count" at 311.82,-1618.13 h95.99
  text "Hole Size" at 701.62,-1618.13 h95.99
  text "Plated" at 1467.04,-1618.13 h95.99
  text "Hole Type" at 1797,-1618.13 h95.99
  text "Drill Layer Pair" at 2277.38,-1618.13 h95.99
  text "Via/Pad" at 2934.48,-1618.13 h95.99
  text "Pad Shape" at 3328.11,-1618.13 h95.99
  text "Template" at 3842.33,-1618.13 h95.99
  text "Description" at 4405.36,-1618.13 h95.99
  text "Hole Tolerance (+)" at 4921.8,-1618.13 h95.99
  text "Hole Tolerance (-)" at 5724.88,-1618.13 h95.99
  text "2" at 311.82,-1783.71 h79.99
  text "40.16mil (1.020mm)" at 701.62,-1783.71 h79.99
  text "PTH" at 1467.04,-1783.71 h79.99
  text "Round" at 1797,-1783.71 h79.99
  text "Top - Bottom" at 2277.38,-1783.71 h79.99
  text "Pad" at 2934.48,-1783.71 h79.99
  text "(Mixed)" at 3328.11,-1783.71 h79.99
  text "(Mixed)" at 3842.33,-1783.71 h79.99
  text "2" at 311.82,-1949.28 h79.99
  text "62.99mil (1.600mm)" at 701.62,-1949.28 h79.99
  text "PTH" at 1467.04,-1949.28 h79.99
  text "Round" at 1797,-1949.28 h79.99
  text "Top - Bottom" at 2277.38,-1949.28 h79.99
  text "Pad" at 2934.48,-1949.28 h79.99
  text "Rounded" at 3328.11,-1949.28 h79.99
  text "c250h160" at 3842.33,-1949.28 h79.99
  text "3" at 311.82,-2114.86 h79.99
  text "28.00mil (0.711mm)" at 701.62,-2114.86 h79.99
  text "PTH" at 1467.04,-2114.86 h79.99
  text "Round" at 1797,-2114.86 h79.99
  text "Top - Bottom" at 2277.38,-2114.86 h79.99
  text "Via" at 2934.48,-2114.86 h79.99
  text "Rounded" at 3328.11,-2114.86 h79.99
  text "v127h71" at 3842.33,-2114.86 h79.99
  text "4" at 311.82,-2280.43 h79.99
  text "40.00mil (1.016mm)" at 701.62,-2280.43 h79.99
  text "PTH" at 1467.04,-2280.43 h79.99
  text "Round" at 1797,-2280.43 h79.99
  text "Top - Bottom" at 2277.38,-2280.43 h79.99
  text "Pad" at 2934.48,-2280.43 h79.99
  text "(Mixed)" at 3328.11,-2280.43 h79.99
  text "(Mixed)" at 3842.33,-2280.43 h79.99
  text "4" at 311.82,-2446.01 h79.99
  text "55.00mil (1.397mm)" at 701.62,-2446.01 h79.99
  text "PTH" at 1467.04,-2446.01 h79.99
  text "Round" at 1797,-2446.01 h79.99
  text "Top - Bottom" at 2277.38,-2446.01 h79.99
  text "Pad" at 2934.48,-2446.01 h79.99
  text "(Mixed)" at 3328.11,-2446.01 h79.99
  text "(Mixed)" at 3842.33,-2446.01 h79.99
  text "3.00mil (0.076mm)" at 4921.8,-2446.01 h79.99
  text "3.00mil (0.076mm)" at 5724.88,-2446.01 h79.99
  text "4" at 311.82,-2611.58 h79.99
  text "152.00mil (3.861mm)" at 701.62,-2611.58 h79.99
  text "PTH" at 1467.04,-2611.58 h79.99
  text "Round" at 1797,-2611.58 h79.99
  text "Top - Bottom" at 2277.38,-2611.58 h79.99
  text "Pad" at 2934.48,-2611.58 h79.99
  text "Rounded" at 3328.11,-2611.58 h79.99
  text "c724h386z508" at 3842.33,-2611.58 h79.99
  text "5" at 311.82,-2777.16 h79.99
  text "29.53mil (0.750mm)" at 701.62,-2777.16 h79.99
  text "PTH" at 1467.04,-2777.16 h79.99
  text "Round" at 1797,-2777.16 h79.99
  text "Top - Bottom" at 2277.38,-2777.16 h79.99
  text "Pad" at 2934.48,-2777.16 h79.99
  text "Rounded" at 3328.11,-2777.16 h79.99
  text "c126h75" at 3842.33,-2777.16 h79.99
  text "DRAWN:" at 10245,-2823 h90
  text "SBS" at 10545,-2833 h90
  text "DATE:" at 10815.44,-2833.51 h90
  text "06/27/2022" at 11034.58,-2833.51 h90
  text "S2Lenel" at 12320,-2870 h90
  text "6" at 311.82,-2942.73 h79.99
  text "27.56mil (0.700mm)" at 701.62,-2942.73 h79.99
  text "PTH" at 1467.04,-2942.73 h79.99
  text "Round" at 1797,-2942.73 h79.99
  text "Top - Bottom" at 2277.38,-2942.73 h79.99
  text "Pad" at 2934.48,-2942.73 h79.99
  text "Rounded" at 3328.11,-2942.73 h79.99
  text "c121h70" at 3842.33,-2942.73 h79.99
  text "CHECKED:" at 10245,-2973 h90
  text "ONE SPEEN ST." at 12330,-2980 h90
  text "DATE:" at 10815.44,-2986.12 h90
  text "FRAMINGHAM, MA 01791" at 12320,-3083 h90
  text "22" at 311.82,-3108.31 h79.99
  text "43.31mil (1.100mm)" at 701.62,-3108.31 h79.99
  text "PTH" at 1467.04,-3108.31 h79.99
  text "Round" at 1797,-3108.31 h79.99
  text "Top - Bottom" at 2277.38,-3108.31 h79.99
  text "Pad" at 2934.48,-3108.31 h79.99
  text "(Mixed)" at 3328.11,-3108.31 h79.99
  text "(Mixed)" at 3842.33,-3108.31 h79.99
  text "CHECKED:" at 10245,-3123 h90
  text "DATE:" at 10817.4,-3128.96 h90
  text "DWG TITLE" at 11522.72,-3176.92 h90
  text "UNLESS OTHERWISE SPECIFIED:" at 10200.76,-3261.72 h90
  text "26" at 311.82,-3273.88 h79.99
  text "35.04mil (0.890mm)" at 701.62,-3273.88 h79.99
  text "PTH" at 1467.04,-3273.88 h79.99
  text "Round" at 1797,-3273.88 h79.99
  text "Top - Bottom" at 2277.38,-3273.88 h79.99
  text "Pad" at 2934.48,-3273.88 h79.99
  text "(Mixed)" at 3328.11,-3273.88 h79.99
  text "(Mixed)" at 3842.33,-3273.88 h79.99
  text "M1-3200 Test Board" at 12370,-3323 h90
  text "DIMENSIONS ARE IN INCHES AND APPLY" at 10200.76,-3357.47 h90
  text "54" at 311.82,-3439.46 h79.99
  text "31.50mil (0.800mm)" at 701.62,-3439.46 h79.99
  text "PTH" at 1467.04,-3439.46 h79.99
  text "Round" at 1797,-3439.46 h79.99
  text "Top - Bottom" at 2277.38,-3439.46 h79.99
  text "Pad" at 2934.48,-3439.46 h79.99
  text "(Mixed)" at 3328.11,-3439.46 h79.99
  text "(Mixed)" at 3842.33,-3439.46 h79.99
  text "AFTER PROCESSING TOLERANCES" at 10197.95,-3453.23 h90
  text "FABRICATION DRAWING" at 12145,-3508 h90
  text "TOLERANCES" at 10281.46,-3590.18 h90
  text "186" at 311.82,-3605.03 h79.99
  text "12.00mil (0.305mm)" at 701.62,-3605.03 h79.99
  text "PTH" at 1467.04,-3605.03 h79.99
  text "Round" at 1797,-3605.03 h79.99
  text "Top - Bottom" at 2277.38,-3605.03 h79.99
  text "Via" at 2934.48,-3605.03 h79.99
  text "Rounded" at 3328.11,-3605.03 h79.99
  text "v61h30" at 3842.33,-3605.03 h79.99
  text ".XXX = +/- .005" at 10820,-3673 h90
  text "SIZE" at 11486.17,-3676.92 h90
  text "DWG NO." at 11712.72,-3676.92 h90
  text ".X   = +/- .1" at 10300.21,-3684.84 h90
  text "Rev" at 13760.17,-3685.92 h90
  text ".XX  = +/- .01" at 10300.58,-3764.3 h90
  text "B" at 13814,-3770 h90
  text "318 Total" at 311.82,-3770.61 h79.99
  text "ANGLES = +/- 2" at 10820,-3773 h90
  text "S2-PC-0000" at 12370,-3783 h90
  text "B" at 11524.18,-3820.59 h90
  text "SCALE:" at 11522.77,-3944.49 h120
  text "1/1" at 11953.87,-3949.13 h120
  text "REMOVE ALL BURRS AND SHARP EDGES" at 10190,-3950 h90
  text "NOTES" at 22872,-8722 h120
  text "NOTES" at 21796.69,-15613.25 h120

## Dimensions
3975,4996 to 3975,-4 on Drill Drawing
-2,4996 to 3975,4996 on Drill Drawing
